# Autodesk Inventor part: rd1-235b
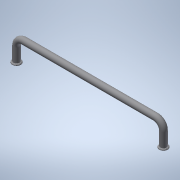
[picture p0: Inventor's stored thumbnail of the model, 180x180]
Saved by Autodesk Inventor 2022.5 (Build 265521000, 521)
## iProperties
Created: 2016-12
Part Number: rd1-235b
Material: 一般
Document SubType Name: Modeling
Designer: imaocorp
Density: 1 g/cm^3
Appearance: 既定
Author: imaocorp
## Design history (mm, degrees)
node "rd1-235b.x_t1"
node "rd1-235b"
node "Base1"
